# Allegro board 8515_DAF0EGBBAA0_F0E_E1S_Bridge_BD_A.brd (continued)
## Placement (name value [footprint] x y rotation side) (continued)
R728  22  [R0402-0201]  116.84 29.34 180 bottom
R729  22  [R0402-0201]  127.38 27.69 90 top
R730  4.7K  [R0402-0201]  127.38 29.72 90 top
R731  4.7K  [R0402-0201]  127.38 29.72 90 bottom
R733  4.7K  [R0402-0201]  120.27 27.69 270 bottom
R734  4.7K  [R0402-0201]  126.36 27.69 90 bottom
R735  4.7K  [R0402-0201]  122.3 29.72 270 bottom
R736  4.7K  [R0402-0201]  120.27 29.72 90 bottom
R737  4.7K  [R0402-0201]  121.28 29.72 90 bottom
R738  4.7K  [R0402-0201]  124.33 29.72 90 bottom
R746  2.87K  [R0402-0201]  115.44 49.02 0 top
R747  2.87K  [R0402-0201]  117.47 51.99 180 top
R749  2K  [R0402-0201]  115.44 48.01 180 top
R750  2K  [R0402-0201]  117.47 51.05 0 top
R751  2.87K  [R0402-0201]  117.47 51.99 180 bottom
R752  60.4K  [R0402-0201]  117.22 36.45 90 top
R753  2K  [R0402-0201]  117.47 51.05 0 bottom
R754  10K  [R0402-0201]  118.24 36.45 270 top
R755  60.4K  [R0402-0201]  115.44 38.1 0 bottom
R756  10K  [R0402-0201]  115.44 37.08 180 bottom
R757  60.4K  [R0402-0201]  115.44 38.1 0 top
R758  10K  [R0402-0201]  115.44 37.08 180 top
R759  60.4K  [R0402-0201]  116.46 42.01 270 top
R760  10K  [R0402-0201]  116.13 40.61 180 top
R765  60.4K  [R0402-0201]  119.51 49.02 180 top
R766  60.4K  [R0402-0201]  117.47 49.02 180 top
R767  2.87K  [R0402-0201]  117.47 49.02 180 bottom
R768  10K  [R0402-0201]  119.51 48.01 0 top
R769  10K  [R0402-0201]  117.47 48.01 0 top
R770  2K  [R0402-0201]  117.47 48.01 0 bottom
R771  2.87K  [R0402-0201]  119.51 49.02 180 bottom
R772  2K  [R0402-0201]  119.51 48.01 0 bottom
R773  4.7K  [R0402-0201]  135.64 47.37 90 top
R774  4.7K  [R0402-0201]  132.59 47.37 90 bottom
R775  4.7K  [R0402-0201]  135.64 47.37 90 bottom
R776  4.7K  [R0402-0201]  144.32 37.8 270 bottom
R777  4.7K  [R0402-0201]  135.64 50.04 270 top
R778  300K  [R0402-0201]  132.53 50.04 90 bottom
R779  4.7K  [R0402-0201]  135.64 50.04 270 bottom
R780  4.7K  [R0402-0201]  145.39 37.8 90 bottom
R781  4.7K  [R0402-0201]  126.36 52.07 270 top
R782  4.7K  [R0402-0201]  123.19 47.37 90 top
R783  4.7K  [R0402-0201]  133.6 47.37 90 top
R784  4.7K  [R0402-0201]  125.22 52.07 90 top
R785  4.7K  [R0402-0201]  124.21 50.04 90 top
R786  300K  [R0402-0201]  123.19 50.04 270 top
R787  4.7K  [R0402-0201]  133.48 50.04 270 top
R788  4.7K  [R0402-0201]  128.52 47.37 270 top
R789  4.7K  [R0402-0201]  124.21 47.37 90 top
R790  4.7K  [R0402-0201]  123.32 29.72 270 bottom
R791  4.7K  [R0402-0201]  126.36 29.72 270 bottom
R792  22  [R0402-0201]  11.33 12.57 270 top
R793  22  [R0402-0201]  14.99 12.57 270 top
R794  22  [R0402-0201]  118.87 33.02 180 bottom
R795  22  [R0402-0201]  135.18 26.37 270 bottom
R796  22  [R0402-0201]  136.09 26.37 270 bottom
R797  22  [R0402-0201]  135.42 20.8 180 bottom
R4580  4.7K  [R0402-0201]  130.18 55.5 180 top
R4581  4.7K  [R0402-0201]  130.18 56.52 180 top
R4582  4.7K  [R0402-0201]  130.18 60.58 180 top
R4583  4.7K  [R0402-0201]  130.18 58.55 180 top
R4584  22  [R0402-0201]  130.18 54.48 180 top
R4585  22  [R0402-0201]  130.18 57.53 180 top
R4586  22  [R0402-0201]  130.18 59.56 180 top
R4587  22  [R0402-0201]  130.18 61.59 180 top
R4588  2K  [R0402-0201]  117.86 38.86 0 top
R4589  22  [R0402-0201]  129.41 29.72 90 bottom
R4591  22  [R0402-0201]  135.42 18.08 180 bottom
R4592  22  [R0402-0201]  135.42 19 180 bottom
R4593  22  [R0402-0201]  118.31 12.53 90 top
R4594  22  [R0402-0201]  129.05 11.67 0 top
R4595  22  [R0402-0201]  113.33 13.67 0 top
R4596  22  [R0402-0201]  115.82 10.82 0 top
R4597  4.7K  [R0402-0201]  135.42 19.91 180 bottom
R4598  4.7K  [R0402-0201]  113.33 14.58 0 top
R4599  4.7K  [R0402-0201]  117.88 10.82 0 top
R4600  4.7K  [R0402-0201]  138.71 22.53 180 bottom
R4601  4.7K  [R0402-0201]  138.71 21.62 180 bottom
R4602  22  [R0402-0201]  12.24 12.57 270 top
R4603  22  [R0402-0201]  14.07 12.57 270 top
R4604  4.7K  [R0402-0201]  142.44 28.29 90 bottom
R4605  4.7K  [R0402-0201]  141.53 28.29 90 bottom
R4607  22  [R0402-0201]  27.53 12.45 270 top
R4608  22  [R0402-0201]  117.88 13.49 90 bottom
R4609  4.7K  [R0402-0201]  109.02 15.19 0 top
R4610  100  [R0402-0201]  108.99 16.18 0 top
R4611  22  [R0402-0201]  107.59 14.55 90 top
R4612  0  [R0402-0201]  118.9 13.49 270 bottom
R4613  1K  [R0402-0201]  134.62 50.04 270 bottom
R4614  47K  [R0402-0201]  133.6 50.04 270 bottom
R4615  4.7K  [R0402-0201]  133.6 47.37 270 bottom
R4616  4.7K  [R0402-0201]  128.52 47.37 270 bottom
R4617  4.7K  [R0402-0201]  129.54 47.37 270 bottom
R4618  4.7K  [R0402-0201]  131.57 50.04 270 bottom
R4619  0  [R0402-0201]  23.65 53.39 180 bottom
R4620  0  [R0402-0201]  19.33 54.28 270 bottom
R4621  10K  [R0402-0201]  18.92 51.89 0 bottom
R4622  1K  [R0402-0201]  23.65 55.22 0 bottom
R4623  0  [R0402-0201]  47.29 50.85 180 bottom
R4624  0  [R0402-0201]  42.19 54.2 0 bottom
R4625  10K  [R0402-0201]  42.19 52.37 0 bottom
R4626  1K  [R0402-0201]  47.29 52.68 180 bottom
R4627  0  [R0402-0201]  71.48 55.17 90 bottom
R4628  0  [R0402-0201]  68.2 59.82 180 bottom
R4629  10K  [R0402-0201]  68.1 57.99 0 bottom
R4630  1K  [R0402-0201]  73.3 55.17 270 bottom
R4631  0  [R0402-0201]  98.55 51.38 180 bottom
R4632  0  [R0402-0201]  91.19 53.04 180 bottom
R4633  10K  [R0402-0201]  91.19 54.1 0 bottom
R4634  1K  [R0402-0201]  98.55 53.21 0 bottom
R4635  0  [R0402-0201]  23.65 54.31 0 bottom
R4636  0  [R0402-0201]  47.29 51.77 180 bottom
R4637  0  [R0402-0201]  72.39 55.17 270 bottom
R4638  0  [R0402-0201]  98.55 52.3 0 bottom
R4639  10K  [R0402-0201]  11.68 37.49 180 top
R4640  0  [R0402-0201]  6.35 36.63 180 top
R4641  0  [R0402-0201]  11.68 36.58 0 top
R4642  0  [R0402-0201]  6.35 35.71 0 top
R4643  1K  [R0402-0201]  6.35 37.54 180 top
R4644  10K  [R0402-0201]  45.21 40.59 0 bottom
R4645  0  [R0402-0201]  45.09 44.83 180 bottom
R4646  0  [R0402-0201]  45.21 42.39 180 bottom
R4647  0  [R0402-0201]  45.1 43.89 0 bottom
R4648  1K  [R0402-0201]  45.09 45.75 180 bottom
R4649  10K  [R0402-0201]  59.87 22.71 0 top
R4650  0  [R0402-0201]  62.66 19.32 180 top
R4651  0  [R0402-0201]  60.76 24.16 270 top
R4652  0  [R0402-0201]  62.66 18.4 180 top
R4653  1K  [R0402-0201]  62.66 20.23 180 top
R4654  10K  [R0402-0201]  92.46 28.02 180 bottom
R4655  0  [R0402-0201]  86.28 27 0 bottom
R4656  0  [R0402-0201]  92.46 26.19 0 bottom
R4657  0  [R0402-0201]  86.28 27.91 0 bottom
R4658  1K  [R0402-0201]  86.28 26.09 180 bottom
R4659  4.7K  [R0402-0201]  138.71 24.36 180 bottom
R4660  4.7K  [R0402-0201]  138.71 23.44 180 bottom
R4661  4.7K  [R0402-0201]  138.71 20.7 180 bottom
R4662  4.7K  [R0402-0201]  145.21 19.86 180 bottom
R4663  4.7K  [R0402-0201]  145.21 20.78 180 bottom
R4664  4.7K  [R0402-0201]  145.21 21.69 180 bottom
R4665  4.7K  [R0402-0201]  145.21 22.61 180 bottom
R4666  4.7K  [R0402-0201]  145.21 23.52 180 bottom
R4667  4.7K  [R0402-0201]  145.21 24.46 180 bottom
R4668  4.7K  [R0402-0201]  145.21 25.78 180 bottom
R4669  4.7K  [R0402-0201]  145.16 28.09 180 bottom
R4670  0  [R0402-0201]  141.94 34.84 0 bottom
R4671  0  [R0402-0201]  2.16 25.96 0 bottom
U3  TPS259540DSGR  [WSON8_TH_0-5_2X2XA]  23.29 58.12 270 top
U4  TPS259540DSGR  [WSON8_TH_0-5_2X2XA]  48.06 57.35 270 top
U5  TPS259540DSGR  [WSON8_TH_0-5_2X2XA]  73.58 57.38 270 top
U6  TPS259540DSGR  [WSON8_TH_0-5_2X2XA]  99.06 57.53 270 top
U7  TPS259520DSGR  [WSON8_TH_0-5_2X2XA]  14.38 45.42 0 top
U8  TPS259520DSGR  [WSON8_TH_0-5_2X2XA]  43.08 43.36 0 top
U9  TPS259520DSGR  [WSON8_TH_0-5_2X2XA]  93.34 32.89 0 top
U10  TPS259520DSGR  [WSON8_TH_0-5_2X2XA]  65.99 26.49 0 top
U11  INA230AIRGTR  [QFN16_THXI]  14.73 50.55 0 top
U12  INA230AIRGTR  [QFN16_THXI]  40.87 48.79 0 top
U13  INA230AIRGTR  [QFN16_THXI]  66.52 31.52 0 top
U14  INA230AIRGTR  [QFN16_THXI]  94.21 39.65 0 top
U15  M24128-BWMN6TP  [SOIC8XH]  124.03 59.59 180 top
U16  TMP75  [MSOP8]  92.68 48.87 180 top
U17  2N7002KW  [SOT323XB]  143.99 32.72 270 bottom
U18  TPS259521DSGR  [WSON8_TH_0-5_2X2XA]  120.93 17.48 90 top
U22  MAX15090BEWI+T  [BGA28_0-5_3-525X2-065]  18.21 57.96 0 top
U23  MAX15090BEWI+T  [BGA28_0-5_3-525X2-065]  42.98 57.45 0 top
U24  MAX15090BEWI+T  [BGA28_0-5_3-525X2-065]  68.5 57.1 0 top
U25  MAX15090BEWI+T  [BGA28_0-5_3-525X2-065]  93.98 57.25 0 top
U26  MAX15090BEWI+T  [BGA28_0-5_3-525X2-065]  14.25 40.54 90 top
U27  MAX15090BEWI+T  [BGA28_0-5_3-525X2-065]  43.33 38.46 90 top
U28  MAX15090BEWI+T  [BGA28_0-5_3-525X2-065]  65.71 21.62 90 top
U29  MAX15090BEWI+T  [BGA28_0-5_3-525X2-065]  92.71 27.76 90 top
U30  MAX15090BEWI+T  [BGA28_0-5_3-525X2-065]  128.19 17.53 180 top
U32  9DBL0452BKILFT  [VFQFPN32_TH_0-5_5X5]  39.37 27.94 0 top
U33  MAX15090BEWI+T  [BGA28_0-5_3-525X2-065]  9.83 29.41 180 top
U34  MP5022AGQV-Z  [QFN22_TH_3X5]  16.8 31.96 180 top
U35  AST1030A1-GP  [BGA256_0-8_13X13]  127.42 38.5 0 top
U36  RT9059GQW  [DFN10_THXE]  124.53 24.45 0 top
U42  NL17SZ08DFT2G  [SC70-5XA]  116.2 12.78 0 top
U43  NL17SZ08DFT2G  [SC70-5XA]  120.85 11.56 0 top
U44  PCA9537DP  [MSOP10]  141.5 23.9 90 bottom
U45  74LVC1G17GW  [TSSOP5]  107.42 19.68 90 top
U46  NL17SZ08DFT2G  [SC70-5XA]  115.56 13.2 180 bottom
U47  74LVC1G17GW  [TSSOP5]  109.65 12.45 270 top
U48  PCA9555  [TSSOP24]  139.5 24.03 0 top
X1  TP_TDR_4P_DIP  [MPKT4_H025P0200]  -9.02 12.71 0 bottom
X2  TP_TDR_4P_DIP  [MPKT4_H025P0200]  -45.21 15.25 180 bottom
X3  TP_TDR_4P_DIP  [MPKT4_H025P0200]  -9.02 20.97 0 top
X4  TP_TDR_4P_DIP  [MPKT4_H025P0200]  -45.21 18.43 180 top
X5  TP_TDR_4P_DIP  [MPKT4_H025P0200]  -48.67 116.64 180 bottom
X6  TP_TDR_4P_DIP  [MPKT4_H025P0200]  -8.67 114.1 0 bottom
X7  TP_TDR_4P_DIP  [MPKT4_H025P0200]  -48.67 119.82 180 top
X8  TP_TDR_4P_DIP  [MPKT4_H025P0200]  -8.67 122.36 0 top

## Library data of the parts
C48-C92 C96 C102 C105 C108-C113 C115 C116 C118 C119 C121 C122 C124 C125 C127-C132 C147-C150 C157-C172 C176-C180 C202-C237 C239 C240 C243 C244 C246 C247 C249-C252 C284-C304 C306-C322 PC72 = CAP_NP
D2 D3 D6 D7 D21 = SMDJ60A
D4 D5 D8 D9 = SCHOTTKY_AC
D10 = LED_12
D11 D24 = LED_0
D22 = SPL1040PT
D23 = ZENER_12
D25 = DIODE
DM4-DM6 ME1 = ME_DUMMY_SYMBOL
GF1 = FCONN168_623403212
GF2 = FCONN140_623403242
H3-H17 = HOLE
J1 = SCONN3_51471181
J2 = CONN10_878311019
J4-J7 = SCONN56_ME1305610101011
J8-J11 J13 J14 J17-J26 = PICOPROBE_B
J12 J15 J16 J27 = TDR_3P_TH2
J29 J30 = DIP_2PIN
L4-L9 = L
OSC1 = OSC-4
PR76 R2 R5-R8 R10 R11 R14-R16 R18-R24 R90 R169-R185 R189-R204 R209-R211 R213-R219 R221-R223 R226-R234 R236-R238 R241-R249 R251-R253 R256-R264 R266-R268 R271-R276 R279-R288 R291-R298 R305-R309 R319 R410-R414 R417 R426-R429 R438-R467 R473-R481 R490-R514 R518-R542 R544 R545 R548 R550-R557 R561-R579 R584 R586 R590 R591 R598-R600 R602 R604 R605 R607 R608 R611 R613 R617 R619-R636 R639-R641 R646 R651 R659-R661 R663-R667 R679-R681 R685 R690 R691 R694-R701 R707-R714 R723-R731 R733-R738 R746 R747 R749-R760 R765-R797 R4588 R4589 R4591-R4605 R4607-R4612 R4619-R4671 = R
Q1 Q2 = MOSFET_NCH_DUAL: signal model: MOSFET_DUAL_6P_SOT363XD_IC_2N70_2N7002KDW
Q3 Q4 U17 = MOSFET_NCH_GDS_ESD_PROTECTED
Q5-Q12 = SSM6N7002KFU
R1 R9 R12 R13 R17 R224 R225 R239 R240 R254 R255 R269 R270 R277 R278 R289 R290 R400-R402 R433 = R: signal model: R_R0402-0201_DISCRETE_22_22
R220 R235 R250 R265 = Q_SP_RES4P
R418-R425 = R: signal model: R_R0402-0201_DISCRETE_33.2_33.2
R559 R560 = R: signal model: R_R0402-0201_DISCRETE_0_0
R596 = R: signal model: R_R0402-0201_DISCRETE_CS21002FB_1K
R674 R4584-R4587 = R: signal model: R_R0402-0201_DISCRETE_CS02202FB_22
R675 = R: signal model: R_R0402-0201_DISCRETE_CS41002JB_100K
R4580-R4583 = R: signal model: R_R0402-0201_DISCRETE_CS31002FB_10K
R4613-R4618 = R: signal model: R_R0402
U3-U10 U18 = TPS259521DSGR
U11-U14 = INA230AIRGTR
U15 = M24128
U16 = TMP75AIDGKR
U22-U30 U33 = MAX15090BEWIT
U32 = 9DBL0452BKILFT
U34 = MP5022AGQVZ
U35 = AST1030A1GP
U36 = RT9059GQW
U42 U43 U46 = NL17SZ08DFT2G
U44 = PCA9537
U45 U47 = SN74LVC1G07
U48 = PCA9555
X1-X8 = TP_TDR_4P_FTS: User Part Number: TP15

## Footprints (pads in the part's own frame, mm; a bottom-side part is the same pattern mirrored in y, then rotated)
BGA28_0-5_3-525X2-065
  round 0.229 smd: A1(-1.5,0.75) A2(-1,0.75) A3(-0.5,0.75) A4(0,0.75) A5(0.5,0.75) A6(1,0.75) A7(1.5,0.75) B1(-1.5,0.25) B2(-1,0.25) B3(-0.5,0.25) B4(0,0.25) B5(0.5,0.25) B6(1,0.25) B7(1.5,0.25) C1(-1.5,-0.25) C2(-1,-0.25) C3(-0.5,-0.25) C4(0,-0.25) C5(0.5,-0.25) C6(1,-0.25) C7(1.5,-0.25) D1(-1.5,-0.75) D2(-1,-0.75) D3(-0.5,-0.75) D4(0,-0.75) D5(0.5,-0.75) D6(1,-0.75) D7(1.5,-0.75)
BGA256_0-8_13X13
  round 0.406 smd: A1(-6,6) A2(-5.2,6) A3(-4.4,6) A4(-3.6,6) A5(-2.8,6) A6(-2,6) A7(-1.2,6) A8(-0.4,6) A9(0.4,6) A10(1.2,6) A11(2,6) A12(2.8,6) A13(3.6,6) A14(4.4,6) A15(5.2,6) A16(6,6) B1(-6,5.2) B2(-5.2,5.2) B3(-4.4,5.2) B4(-3.6,5.2) B5(-2.8,5.2) B6(-2,5.2) B7(-1.2,5.2) B8(-0.4,5.2) B9(0.4,5.2) B10(1.2,5.2) B11(2,5.2) B12(2.8,5.2) B13(3.6,5.2) B14(4.4,5.2) B15(5.2,5.2) B16(6,5.2) C1(-6,4.4) C2(-5.2,4.4) C3(-4.4,4.4) C4(-3.6,4.4) C5(-2.8,4.4) C6(-2,4.4) C7(-1.2,4.4) C8(-0.4,4.4) C9(0.4,4.4) C10(1.2,4.4) C11(2,4.4) C12(2.8,4.4) C13(3.6,4.4) C14(4.4,4.4) C15(5.2,4.4) C16(6,4.4) D1(-6,3.6) D2(-5.2,3.6) D3(-4.4,3.6) D4(-3.6,3.6) D5(-2.8,3.6) D6(-2,3.6) D7(-1.2,3.6) D8(-0.4,3.6) D9(0.4,3.6) D10(1.2,3.6) D11(2,3.6) D12(2.8,3.6) D13(3.6,3.6) D14(4.4,3.6) D15(5.2,3.6) D16(6,3.6) E1(-6,2.8) E2(-5.2,2.8) E3(-4.4,2.8) E4(-3.6,2.8) E5(-2.8,2.8) E6(-2,2.8) E7(-1.2,2.8) E8(-0.4,2.8) E9(0.4,2.8) E10(1.2,2.8) E11(2,2.8) E12(2.8,2.8) E13(3.6,2.8) E14(4.4,2.8) E15(5.2,2.8) E16(6,2.8) F1(-6,2) F2(-5.2,2) F3(-4.4,2) F4(-3.6,2) F5(-2.8,2) F6(-2,2) F7(-1.2,2) F8(-0.4,2) F9(0.4,2) F10(1.2,2) F11(2,2) F12(2.8,2) F13(3.6,2) F14(4.4,2) F15(5.2,2) F16(6,2) G1(-6,1.2) G2(-5.2,1.2) G3(-4.4,1.2) G4(-3.6,1.2) G5(-2.8,1.2) G6(-2,1.2) G7(-1.2,1.2) G8(-0.4,1.2) G9(0.4,1.2) G10(1.2,1.2) G11(2,1.2) G12(2.8,1.2) G13(3.6,1.2) G14(4.4,1.2) G15(5.2,1.2) G16(6,1.2) H1(-6,0.4) H2(-5.2,0.4) H3(-4.4,0.4) H4(-3.6,0.4) H5(-2.8,0.4) H6(-2,0.4) H7(-1.2,0.4) H8(-0.4,0.4) H9(0.4,0.4) H10(1.2,0.4) H11(2,0.4) H12(2.8,0.4) H13(3.6,0.4) H14(4.4,0.4) H15(5.2,0.4) H16(6,0.4) J1(-6,-0.4) J2(-5.2,-0.4) J3(-4.4,-0.4) J4(-3.6,-0.4) J5(-2.8,-0.4) J6(-2,-0.4) J7(-1.2,-0.4) J8(-0.4,-0.4) J9(0.4,-0.4) J10(1.2,-0.4) J11(2,-0.4) J12(2.8,-0.4) J13(3.6,-0.4) J14(4.4,-0.4) J15(5.2,-0.4) J16(6,-0.4) K1(-6,-1.2) K2(-5.2,-1.2) K3(-4.4,-1.2) K4(-3.6,-1.2) K5(-2.8,-1.2) K6(-2,-1.2) K7(-1.2,-1.2) K8(-0.4,-1.2) K9(0.4,-1.2) K10(1.2,-1.2) K11(2,-1.2) K12(2.8,-1.2) K13(3.6,-1.2) K14(4.4,-1.2) K15(5.2,-1.2) K16(6,-1.2) L1(-6,-2) L2(-5.2,-2) L3(-4.4,-2) L4(-3.6,-2) L5(-2.8,-2) L6(-2,-2) L7(-1.2,-2) L8(-0.4,-2) L9(0.4,-2) L10(1.2,-2) L11(2,-2) L12(2.8,-2) L13(3.6,-2) L14(4.4,-2) L15(5.2,-2) L16(6,-2) M1(-6,-2.8) M2(-5.2,-2.8) M3(-4.4,-2.8) M4(-3.6,-2.8) M5(-2.8,-2.8) M6(-2,-2.8) M7(-1.2,-2.8) M8(-0.4,-2.8) M9(0.4,-2.8) M10(1.2,-2.8) M11(2,-2.8) M12(2.8,-2.8) M13(3.6,-2.8) M14(4.4,-2.8) M15(5.2,-2.8) M16(6,-2.8) N1(-6,-3.6) N2(-5.2,-3.6) N3(-4.4,-3.6) N4(-3.6,-3.6) N5(-2.8,-3.6) N6(-2,-3.6) N7(-1.2,-3.6) N8(-0.4,-3.6) N9(0.4,-3.6) N10(1.2,-3.6) N11(2,-3.6) N12(2.8,-3.6) N13(3.6,-3.6) N14(4.4,-3.6) N15(5.2,-3.6) N16(6,-3.6) P1(-6,-4.4) P2(-5.2,-4.4) P3(-4.4,-4.4) P4(-3.6,-4.4) P5(-2.8,-4.4) P6(-2,-4.4) P7(-1.2,-4.4) P8(-0.4,-4.4) P9(0.4,-4.4) P10(1.2,-4.4) P11(2,-4.4) P12(2.8,-4.4) P13(3.6,-4.4) P14(4.4,-4.4) P15(5.2,-4.4) P16(6,-4.4) R1(-6,-5.2) R2(-5.2,-5.2) R3(-4.4,-5.2) R4(-3.6,-5.2) R5(-2.8,-5.2) R6(-2,-5.2) R7(-1.2,-5.2) R8(-0.4,-5.2) R9(0.4,-5.2) R10(1.2,-5.2) R11(2,-5.2) R12(2.8,-5.2) R13(3.6,-5.2) R14(4.4,-5.2) R15(5.2,-5.2) R16(6,-5.2) T1(-6,-6) T2(-5.2,-6) T3(-4.4,-6) T4(-3.6,-6) T5(-2.8,-6) T6(-2,-6) T7(-1.2,-6) T8(-0.4,-6) T9(0.4,-6) T10(1.2,-6) T11(2,-6) T12(2.8,-6) T13(3.6,-6) T14(4.4,-6) T15(5.2,-6) T16(6,-6)
C0402
  rect 0.457x0.508 smd: 1(-0.4,0) 2(0.4,0)
C0402-0201
  custom 0.125x0.125 smd: 1(-0.4,0) 2(0.4,0)
C0402_OCTAGONXA
  custom 0.104x0.104 smd: 1(-0.4,0) 2(0.4,0)
C0603
  rect 0.813x0.711 smd: 1(-0.737,0) 2(0.737,0)
C0805_H57
  rect 1.016x1.27 smd: 1(-0.889,0) 2(0.889,0)
C0805_H61
  rect 1.118x1.372 smd: 1(-0.95,0) 2(0.95,0)
CON_F56S2H4D_P0-6W4-6_LUHXA
  round 1.118 hole 1.118 unplated: (-1.75,9.815) (0,-9.815)
  rect 1.27x0.381 smd: A1(2.3,7.995) A2(2.3,7.395) A3(2.3,6.795) A4(2.3,6.195) A5(2.3,5.595) A6(2.3,4.995) A7(2.3,4.395) A8(2.3,3.795) A9(2.3,3.195) A10(2.3,2.595) A11(2.3,1.995) A12(2.3,1.395) A13(2.3,0.795) A14(2.3,0.195) A15(2.3,-0.405) A16(2.3,-1.005) A17(2.3,-1.605) A18(2.3,-2.205) A19(2.3,-2.805) A20(2.3,-3.405) A21(2.3,-4.005) A22(2.3,-4.605) A23(2.3,-5.205) A24(2.3,-5.805) A25(2.3,-6.405) A26(2.3,-7.005) A27(2.3,-7.605) A28(2.3,-8.205) B1(-2.3,7.995) B2(-2.3,7.395) B3(-2.3,6.795) B4(-2.3,6.195) B5(-2.3,5.595) B6(-2.3,4.995) B7(-2.3,4.395) B8(-2.3,3.795) B9(-2.3,3.195) B10(-2.3,2.595) B11(-2.3,1.995) B12(-2.3,1.395) B13(-2.3,0.795) B14(-2.3,0.195) B15(-2.3,-0.405) B16(-2.3,-1.005) B17(-2.3,-1.605) B18(-2.3,-2.205) B19(-2.3,-2.805) B20(-2.3,-3.405) B21(-2.3,-4.005) B22(-2.3,-4.605) B23(-2.3,-5.205) B24(-2.3,-5.805) B25(-2.3,-6.405) B26(-2.3,-7.005) B27(-2.3,-7.605) B28(-2.3,-8.205)
  oval 3.48x1.626 hole 2.464x1.118: G1(0,11.365) G2(0,-11.365)
D_SMCJ170
  rect 2.515x3.302 smd: 1(-3.4,0) 2(3.4,0)
DFN10_THXE
  rect 0.914x0.279 smd: 1(-1.55,1) 2(-1.55,0.5) 3(-1.55,0) 4(-1.55,-0.5) 5(-1.55,-1) 6(1.55,-1) 7(1.55,-0.5) 8(1.55,0) 9(1.55,0.5) 10(1.55,1)
  rect 1.753x2.667 smd: TH(0,0)
GOLD_140P_6-2340324-2
  rect 0.381x2.134 smd: A1(-18.205,-4.135) A4(-16.405,-4.135) A7(-14.605,-4.135) A10(-12.805,-4.135) A13(-11.005,-4.135) A16(-9.205,-4.135) A19(-7.405,-4.135) A22(-5.605,-4.135) A25(-3.805,-4.135) A28(-2.005,-4.135) A29(2.005,-4.135) A32(3.805,-4.135) A35(5.605,-4.135) A38(7.405,-4.135) A41(9.205,-4.135) A43(14.715,-4.135) A46(16.515,-4.135) A49(18.315,-4.135) A52(20.115,-4.135) A55(21.915,-4.135) A58(23.715,-4.135) A61(25.515,-4.135) A64(27.315,-4.135) A67(29.115,-4.135) A70(30.915,-4.135) B1(-18.205,-4.135) B4(-16.405,-4.135) B7(-14.605,-4.135) B10(-12.805,-4.135) B13(-11.005,-4.135) B16(-9.205,-4.135) B19(-7.405,-4.135) B22(-5.605,-4.135) B25(-3.805,-4.135) B28(-2.005,-4.135) B29(2.005,-4.135) B32(3.805,-4.135) B35(5.605,-4.135) B38(7.405,-4.135) B41(9.205,-4.135) B43(14.715,-4.135) B46(16.515,-4.135) B49(18.315,-4.135) B52(20.115,-4.135) B55(21.915,-4.135) B58(23.715,-4.135) B61(25.515,-4.135) B64(27.315,-4.135) B67(29.115,-4.135) B70(30.915,-4.135)
  rect 0.381x1.727 smd: A2(-17.605,-3.935) A3(-17.005,-3.935) A5(-15.805,-3.935) A6(-15.205,-3.935) A8(-14.005,-3.935) A9(-13.405,-3.935) A11(-12.205,-3.935) A12(-11.605,-3.935) A14(-10.405,-3.935) A15(-9.805,-3.935) A17(-8.605,-3.935) A18(-8.005,-3.935) A20(-6.805,-3.935) A21(-6.205,-3.935) A23(-5.005,-3.935) A24(-4.405,-3.935) A26(-3.205,-3.935) A27(-2.605,-3.935) A30(2.605,-3.935) A31(3.205,-3.935) A33(4.405,-3.935) A34(5.005,-3.935) A36(6.205,-3.935) A37(6.805,-3.935) A39(8.005,-3.935) A40(8.605,-3.935) A42(9.805,-3.935) A44(15.315,-3.935) A45(15.915,-3.935) A47(17.115,-3.935) A48(17.715,-3.935) A50(18.915,-3.935) A51(19.515,-3.935) A53(20.715,-3.935) A54(21.315,-3.935) A56(22.515,-3.935) A57(23.115,-3.935) A59(24.315,-3.935) A60(24.915,-3.935) A62(26.115,-3.935) A63(26.715,-3.935) A65(27.915,-3.935) A66(28.515,-3.935) A68(29.715,-3.935) A69(30.315,-3.935) B2(-17.605,-3.935) B3(-17.005,-3.935) B5(-15.805,-3.935) B6(-15.205,-3.935) B8(-14.005,-3.935) B9(-13.405,-3.935) B11(-12.205,-3.935) B12(-11.605,-3.935) B14(-10.405,-3.935) B15(-9.805,-3.935) B17(-8.605,-3.935) B18(-8.005,-3.935) B20(-6.805,-3.935) B21(-6.205,-3.935) B23(-5.005,-3.935) B24(-4.405,-3.935) B26(-3.205,-3.935) B27(-2.605,-3.935) B30(2.605,-3.935) B31(3.205,-3.935) B33(4.405,-3.935) B34(5.005,-3.935) B36(6.205,-3.935) B37(6.805,-3.935) B39(8.005,-3.935) B40(8.605,-3.935) B42(9.805,-3.935) B44(15.315,-3.935) B45(15.915,-3.935) B47(17.115,-3.935) B48(17.715,-3.935) B50(18.915,-3.935) B51(19.515,-3.935) B53(20.715,-3.935) B54(21.315,-3.935) B56(22.515,-3.935) B57(23.115,-3.935) B59(24.315,-3.935) B60(24.915,-3.935) B62(26.115,-3.935) B63(26.715,-3.935) B65(27.915,-3.935) B66(28.515,-3.935) B68(29.715,-3.935) B69(30.315,-3.935)
GOLD_168P_6-2340321-2
  rect 0.381x2.134 smd: A1(-18.205,-4.135) A4(-16.405,-4.135) A7(-14.605,-4.135) A10(-12.805,-4.135) A13(-11.005,-4.135) A16(-9.205,-4.135) A19(-7.405,-4.135) A22(-5.605,-4.135) A25(-3.805,-4.135) A28(-2.005,-4.135) A29(2.005,-4.135) A32(3.805,-4.135) A35(5.605,-4.135) A38(7.405,-4.135) A41(9.205,-4.135) A43(14.715,-4.135) A46(16.515,-4.135) A49(18.315,-4.135) A52(20.115,-4.135) A55(21.915,-4.135) A58(23.715,-4.135) A61(25.515,-4.135) A64(27.315,-4.135) A67(29.115,-4.135) A70(30.915,-4.135) B1(-18.205,-4.135) B4(-16.405,-4.135) B7(-14.605,-4.135) B10(-12.805,-4.135) B13(-11.005,-4.135) B16(-9.205,-4.135) B19(-7.405,-4.135) B22(-5.605,-4.135) B25(-3.805,-4.135) B28(-2.005,-4.135) B29(2.005,-4.135) B32(3.805,-4.135) B35(5.605,-4.135) B38(7.405,-4.135) B41(9.205,-4.135) B43(14.715,-4.135) B46(16.515,-4.135) B49(18.315,-4.135) B52(20.115,-4.135) B55(21.915,-4.135) B58(23.715,-4.135) B61(25.515,-4.135) B64(27.315,-4.135) B67(29.115,-4.135) B70(30.915,-4.135) OCP_A6(-27.4,-4.135) OCP_A10(-25,-4.135) OCP_A13(-23.2,-4.135) OCP_B10(-25,-4.135) OCP_B13(-23.2,-4.135)
  rect 0.381x1.727 smd: A2(-17.605,-3.935) A3(-17.005,-3.935) A5(-15.805,-3.935) A6(-15.205,-3.935) A8(-14.005,-3.935) A9(-13.405,-3.935) A11(-12.205,-3.935) A12(-11.605,-3.935) A14(-10.405,-3.935) A15(-9.805,-3.935) A17(-8.605,-3.935) A18(-8.005,-3.935) A20(-6.805,-3.935) A21(-6.205,-3.935) A23(-5.005,-3.935) A24(-4.405,-3.935) A26(-3.205,-3.935) A27(-2.605,-3.935) A30(2.605,-3.935) A31(3.205,-3.935) A33(4.405,-3.935) A34(5.005,-3.935) A36(6.205,-3.935) A37(6.805,-3.935) A39(8.005,-3.935) A40(8.605,-3.935) A42(9.805,-3.935) A44(15.315,-3.935) A45(15.915,-3.935) A47(17.115,-3.935) A48(17.715,-3.935) A50(18.915,-3.935) A51(19.515,-3.935) A53(20.715,-3.935) A54(21.315,-3.935) A56(22.515,-3.935) A57(23.115,-3.935) A59(24.315,-3.935) A60(24.915,-3.935) A62(26.115,-3.935) A63(26.715,-3.935) A65(27.915,-3.935) A66(28.515,-3.935) A68(29.715,-3.935) A69(30.315,-3.935) B2(-17.605,-3.935) B3(-17.005,-3.935) B5(-15.805,-3.935) B6(-15.205,-3.935) B8(-14.005,-3.935) B9(-13.405,-3.935) B11(-12.205,-3.935) B12(-11.605,-3.935) B14(-10.405,-3.935) B15(-9.805,-3.935) B17(-8.605,-3.935) B18(-8.005,-3.935) B20(-6.805,-3.935) B21(-6.205,-3.935) B23(-5.005,-3.935) B24(-4.405,-3.935) B26(-3.205,-3.935) B27(-2.605,-3.935) B30(2.605,-3.935) B31(3.205,-3.935) B33(4.405,-3.935) B34(5.005,-3.935) B36(6.205,-3.935) B37(6.805,-3.935) B39(8.005,-3.935) B40(8.605,-3.935) B42(9.805,-3.935) B44(15.315,-3.935) B45(15.915,-3.935) B47(17.115,-3.935) B48(17.715,-3.935) B50(18.915,-3.935) B51(19.515,-3.935) B53(20.715,-3.935) B54(21.315,-3.935) B56(22.515,-3.935) B57(23.115,-3.935) B59(24.315,-3.935) B60(24.915,-3.935) B62(26.115,-3.935) B63(26.715,-3.935) B65(27.915,-3.935) B66(28.515,-3.935) B68(29.715,-3.935) B69(30.315,-3.935) OCP_A1(-30.4,-3.935) OCP_A2(-29.8,-3.935) OCP_A3(-29.2,-3.935) OCP_A4(-28.6,-3.935) OCP_A5(-28,-3.935) OCP_A7(-26.8,-3.935) OCP_A8(-26.2,-3.935) OCP_A9(-25.6,-3.935) OCP_A11(-24.4,-3.935) OCP_A12(-23.8,-3.935) OCP_A14(-22.6,-3.935) OCP_B1(-30.4,-3.935) OCP_B2(-29.8,-3.935) OCP_B3(-29.2,-3.935) OCP_B4(-28.6,-3.935) OCP_B5(-28,-3.935) OCP_B6(-27.4,-3.935) OCP_B7(-26.8,-3.935) OCP_B8(-26.2,-3.935) OCP_B9(-25.6,-3.935) OCP_B11(-24.4,-3.935) OCP_B12(-23.8,-3.935) OCP_B14(-22.6,-3.935)
HEADER1X2XJ_H339
  rect 1.549x1.549 hole 1.041: 1(0,0)
  round 1.549 hole 1.041: 2(0,-2.54)
HEADER1X3SXE_H367
  rect 2.769x1.016 smd: 1(-1.375,2.54) 2(1.375,0) 3(-1.375,-2.54)
HEADER2X5SXM
  rect 2.591x0.711 smd: 1(-1.712,2.54) 2(1.712,2.54) 3(-1.712,1.27) 4(1.712,1.27) 5(-1.712,0) 6(1.712,0) 7(-1.712,-1.27) 8(1.712,-1.27) 9(-1.712,-2.54) 10(1.712,-2.54)
HOLE_C5D2B4_R2-23X5T_NPM
  custom 1.181x1.181 hole 2.007: 1(0,0)
HOLE_C7-5D3_5B7_OB7XC4-75TC3-5B_NPM_SPD
  custom 2.375x2.375 hole 3.023: 1(0,0)
HOLE_C8D3-3B10_NPM
  round 8.001 hole 3.302: 1(0,0)
HOLE_C10-2D6-4B10_R5-6X10B_NPB
  round 10.211 hole 6.401: 1(0,0)
L0402
  rect 0.457x0.508 smd: 1(-0.4,0) 2(0.4,0)
L0603
  rect 0.813x0.711 smd: 1(-0.737,0) 2(0.737,0)
L0805
  rect 1.118x1.372 smd: 1(-0.95,0) 2(0.95,0)
LED_19217_H22
  rect 0.813x0.813 smd: A(-0.75,0) C(0.75,0)
LED_LTSTS270KSKT
  rect 0.914x0.914 smd: 1(-0.9,0) 2(0.9,0)
MPKT4_H025P0200
  round 1.003 hole 0.25: 1(0,0) 4(0,-2.54)
  round 1.994 hole 0.25: 2(2.54,0) 3(2.54,-2.54)
MSOP8
  rect 1.422x0.356 smd: 1(-2.232,0.975) 2(-2.232,0.325) 3(-2.232,-0.325) 4(-2.232,-0.975) 5(2.232,-0.975) 6(2.232,-0.325) 7(2.232,0.325) 8(2.232,0.975)
MSOP10
  rect 1.448x0.279 smd: 1(-2.225,1) 2(-2.225,0.5) 3(-2.225,0) 4(-2.225,-0.5) 5(-2.225,-1) 6(2.225,-1) 7(2.225,-0.5) 8(2.225,0) 9(2.225,0.5) 10(2.225,1)
OSC4_FJ2500009
  rect 1.016x1.219 smd: 1(-0.65,0.85) 2(-0.65,-0.85) 3(0.65,-0.85) 4(0.65,0.85)
POWERDI5XA
  rect 1.397x1.422 smd: 1(-2.856,0.92) 2(-2.856,-0.92)
  rect 4.877x3.378 smd: 3(1.126,0)
QFN16_THXI
  rect 0.838x0.254 smd: 1(-1.475,0.75) 2(-1.475,0.25) 3(-1.475,-0.25) 4(-1.475,-0.75) 9(1.475,-0.75) 10(1.475,-0.25) 11(1.475,0.25) 12(1.475,0.75)
  rect 0.254x0.838 smd: 5(-0.75,-1.475) 6(-0.25,-1.475) 7(0.25,-1.475) 8(0.75,-1.475) 13(0.75,1.475) 14(0.25,1.475) 15(-0.25,1.475) 16(-0.75,1.475)
  rect 1.702x1.702 smd: TH(0,0)
QFN22_TH_3X5
  custom 0.062x0.062 smd: 1(-1.375,2)
  rect 0.813x0.254 smd: 2(-1.4,1.5) 3(-1.4,1) 4(-1.4,0.5) 5(-1.4,0) 6(-1.4,-0.5) 7(-1.4,-1) 8(-1.4,-1.5) 9(-1.4,-2) 12(1.4,-2) 13(1.4,-1.5) 14(1.4,-1) 15(1.4,-0.5) 16(1.4,0) 17(1.4,0.5) 18(1.4,1) 19(1.4,1.5) 20(1.4,2)
  rect 0.254x0.813 smd: 10(-0.5,-2.4) 11(0.5,-2.4)
  custom 0.231x0.231 smd: 21_22(0.5,2.338)
  rect 1.27x0.254 smd: 23(0,1.1) 24(0,0.2) 25(0,-0.7) 26(0,-1.6)
R0402-0201
  custom 0.125x0.125 smd: 1(-0.4,0) 2(0.4,0)
R0603
  rect 0.813x0.711 smd: 1(-0.737,0) 2(0.737,0)
R0603_H24
  rect 0.813x0.711 smd: 1(-0.737,0) 2(0.737,0)
R1206XI
  rect 0.914x1.6 smd: 1(-1.45,0) 2(1.45,0)
R1206XO_4P_SHORT
  rect 1.499x2.007 smd: 1A(-1.7,0) 2A(1.7,0)
  rect 0.254x0.508 smd: 1B(-1.078,0) 2B(1.078,0)
SC70-5XA
  rect 0.508x0.406 smd: 1(-0.95,0.65) 2(-0.95,0) 3(-0.95,-0.65) 4(0.95,-0.65) 5(0.95,0.65)
SOD123_2-65X1-6
  rect 1.499x1.499 smd: A(-1.95,0) C(1.95,0)
SOD123F
  rect 1.321x1.422 smd: A(-1.45,0) C(1.45,0)
SOD323XB
  rect 1.372x0.66 smd: 1(-1.2,0) 2(1.2,0)
SOIC8XH
  rect 1.27x0.889 smd: 1(-2.6,1.905) 2(-2.6,0.635) 3(-2.6,-0.635) 4(-2.6,-1.905) 5(2.6,-1.905) 6(2.6,-0.635) 7(2.6,0.635) 8(2.6,1.905)
SOT323XB
  rect 0.813x0.61 smd: D(0.8,0) G(-0.8,0.65) S(-0.8,-0.65)
SOT363_0-65_2X1-25XB
  rect 0.813x0.406 smd: 1(-0.95,0.65) 2(-0.95,0) 3(-0.95,-0.65) 4(0.95,-0.65) 5(0.95,0) 6(0.95,0.65)
SOT363XB
  rect 0.61x0.61 smd: 1(-0.9,0.75) 3(-0.9,-0.75) 4(0.9,-0.75) 6(0.9,0.75)
  rect 0.61x0.406 smd: 2(-0.9,0) 5(0.9,0)
TDR_3P_C85P67_141_100M_Q
  round 2.159 hole 1.702: 1(0,0) 2(-1.27,3.349) 3(1.27,3.349)
TRIANG_LAUNCH_3PXA
  round 0.254 hole 0.991 unplated: (-1.274,3.852) (-1.274,-2.498) (-0.004,-5.038) (1.266,3.852) (1.266,-2.498)
  round 0.66 smd: 1(-0.512,1.301) 2(0.504,1.301)
  rect 0.991x1.499 smd: 3(-0.004,-0.148)
TSSOP5
  rect 1.245x0.356 smd: 1(-0.945,0.65) 2(-0.945,0) 3(-0.945,-0.65) 4(0.945,-0.65) 5(0.945,0.65)
TSSOP24
  rect 1.499x0.356 smd: 1(-2.921,3.575) 2(-2.921,2.925) 3(-2.921,2.275) 4(-2.921,1.625) 5(-2.921,0.975) 6(-2.921,0.325) 7(-2.921,-0.325) 8(-2.921,-0.975) 9(-2.921,-1.625) 10(-2.921,-2.275) 11(-2.921,-2.925) 12(-2.921,-3.575) 13(2.921,-3.575) 14(2.921,-2.925) 15(2.921,-2.275) 16(2.921,-1.625) 17(2.921,-0.975) 18(2.921,-0.325) 19(2.921,0.325) 20(2.921,0.975) 21(2.921,1.625) 22(2.921,2.275) 23(2.921,2.925) 24(2.921,3.575)
unnamed#2
  round 0.991 smd: 1(0,0)
unnamed#3
  round 0 smd: (5,-5)
unnamed#4
  round 0 smd: (5,5)
unnamed#5
  round 0 smd: (-5,-5)
unnamed#6
  round 0 smd: (-5,5)
VFQFPN32_TH_0-5_5X5
  custom 0.07x0.07 smd: 1(-2.45,1.75) 2(-2.45,1.25) 3(-2.45,0.75) 4(-2.45,0.25) 5(-2.45,-0.25) 6(-2.45,-0.75) 7(-2.45,-1.25) 8(-2.45,-1.75) 9(-1.75,-2.45) 10(-1.25,-2.45) 11(-0.75,-2.45) 12(-0.25,-2.45) 13(0.25,-2.45) 14(0.75,-2.45) 15(1.25,-2.45) 16(1.75,-2.45) 17(2.45,-1.75) 18(2.45,-1.25) 19(2.45,-0.75) 20(2.45,-0.25) 21(2.45,0.25) 22(2.45,0.75) 23(2.45,1.25) 24(2.45,1.75) 25(1.75,2.45) 26(1.25,2.45) 27(0.75,2.45) 28(0.25,2.45) 29(-0.25,2.45) 30(-0.75,2.45) 31(-1.25,2.45) 32(-1.75,2.45)
  rect 3.302x3.302 smd: TH(0,0)
WSON8_TH_0-5_2X2XA
  custom 0.062x0.062 smd: 1(-0.95,0.75) 2(-0.95,0.25) 3(-0.95,-0.25) 4(-0.95,-0.75) 5(0.95,-0.75) 6(0.95,-0.25) 7(0.95,0.25) 8(0.95,0.75)
  custom 0.225x0.225 smd: TH(0,0)

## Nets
GND: C48.2 C49.2 C50.2 C51.2 C52.2 C53.2 C54.2 C55.2 C56.2 C57.2 C58.2 C59.2 C60.2 C61.2 C62.2 C63.2 C64.2 C65.2 C66.2 C67.2 C68.2 C69.2 C70.2 C71.2 C72.2 C73.2 C75.2 C76.2 C78.2 C79.2 C81.2 C82.2 C84.1 C85.2 C86.1 C87.1 C88.2 C89.2 C90.2 C91.2 C92.2 C96.1 C102.1 C105.1 C108.1 C109.2 C110.2 C111.2 C112.2 C113.1 C115.2 C116.1 C118.2 C119.1 C121.2 C122.1 C124.2 C125.1 C127.2 C128.1 C129.1 C130.1 C131.1 C132.1 C147.2 C148.2 C149.2 C150.2 C157.2 C158.2 C159.2 C160.2 C161.2 C162.2 C163.2 C164.1 C165.1 C166.1 C167.1 C168.1 C169.2 C170.1 C171.2 C172.2 C176.2 C177.2 C178.1 C179.1 C180.2 C202.2 C204.2 C205.2 C207.2 C208.2 C209.2 C210.2 C211.2 C212.2 C213.2 C214.2 C215.2 C216.2 C217.2 C218.2 C219.2 C220.2 C221.2 C222.2 C223.2 C224.2 C225.2 C226.2 C227.2 C228.2 C229.2 C230.2 C231.2 C232.2 C233.2 C234.2 C235.2 C236.2 C237.2 C239.2 C240.2 C243.2 C244.2 C246.2 C247.2 C249.2 C250.2 C251.2 C252.2 C284.1 C285.1 C286.1 C287.1 C288.1 C289.1 C290.1 C291.1 C292.1 C293.1 C294.1 C295.2 C296.1 C297.2 C298.2 C299.2 C300.2 C301.2 C302.2 C303.2 C304.2 C306.2 C307.2 C308.2 C309.2 C310.1 C311.2 C312.2 C313.2 C314.2 C315.2 C316.2 C317.2 C318.2 C319.2 C320.2 C321.2 C322.2 D2.A D3.A D4.A D5.A D6.A D7.A D8.A D9.A D10.2 D21.A D22.1 D22.2 D23.1 GF1.A1 GF1.A2 GF1.A3 GF1.A4 GF1.A5 GF1.A6 GF1.A13 GF1.A16 GF1.A19 GF1.A22 GF1.A25 GF1.A28 GF1.A29 GF1.A32 GF1.A35 GF1.A38 GF1.A41 GF1.A43 GF1.A46 GF1.A49 GF1.A52 GF1.A55 GF1.A58 GF1.A61 GF1.A64 GF1.A67 GF1.B13 GF1.B16 GF1.B19 GF1.B22 GF1.B25 GF1.B28 GF1.B29 GF1.B32 GF1.B35 GF1.B38 GF1.B41 GF1.B43 GF1.B46 GF1.B49 GF1.B52 GF1.B55 GF1.B58 GF1.B61 GF1.B64 GF1.B67 GF1.OCP_A10 GF1.OCP_A13 GF1.OCP_B10 GF1.OCP_B13 GF2.A1 GF2.A2 GF2.A3 GF2.A4 GF2.A5 GF2.A6 GF2.A13 GF2.A16 GF2.A19 GF2.A22 GF2.A25 GF2.A28 GF2.A29 GF2.A32 GF2.A35 GF2.A38 GF2.A41 GF2.A43 GF2.A46 GF2.A49 GF2.A52 GF2.A55 GF2.A58 GF2.A61 GF2.A64 GF2.A67 GF2.B13 GF2.B16 GF2.B19 GF2.B22 GF2.B25 GF2.B28 GF2.B29 GF2.B32 GF2.B35 GF2.B38 GF2.B41 GF2.B43 GF2.B46 GF2.B49 GF2.B52 GF2.B55 GF2.B58 GF2.B61 GF2.B64 GF2.B67 H3.1(\GND\) H4.1(\GND\) H5.1(\GND\) H6.1(\GND\) H7.1(\GND\) H8.1(\GND\) H9.1(\GND\) H10.1(\GND\) H11.1(\GND\) H12.1(\GND\) H13.1(\GND\) H14.1(\GND\) H15.1(\GND\) H16.1(\GND\) H17.1(\GND\) J1.2 J2.3 J2.5 J4.A1 J4.A2 J4.A3 J4.A4 J4.A5 J4.A6 J4.A13 J4.A16 J4.A19 J4.A22 J4.A25 J4.A28 J4.B13 J4.B16 J4.B19 J4.B22 J4.B25 J4.B28 J4.G1 J4.G2 J5.A1 J5.A2 J5.A3 J5.A4 J5.A5 J5.A6 J5.A13 J5.A16 J5.A19 J5.A22 J5.A25 J5.A28 J5.B13 J5.B16 J5.B19 J5.B22 J5.B25 J5.B28 J5.G1 J5.G2 J6.A1 J6.A2 J6.A3 J6.A4 J6.A5 J6.A6 J6.A13 J6.A16 J6.A19 J6.A22 J6.A25 J6.A28 J6.B13 J6.B16 J6.B19 J6.B22 J6.B25 J6.B28 J6.G1 J6.G2 J7.A1 J7.A2 J7.A3 J7.A4 J7.A5 J7.A6 J7.A13 J7.A16 J7.A19 J7.A22 J7.A25 J7.A28 J7.B13 J7.B16 J7.B19 J7.B22 J7.B25 J7.B28 J7.G1 J7.G2 OSC1.2 PC72.2 Q3.S(\S\) Q4.S(\S\) Q5.1 Q5.4 Q6.1 Q6.4 Q7.1 Q7.4 Q8.1 Q8.4 Q9.1 Q9.4 Q10.1 Q10.4 Q11.1 Q11.4 Q12.1 Q12.4 R11.2 R169.1 R172.1 R175.2 R176.2 R177.1 R180.1 R183.2 R184.2 R189.2 R192.2 R195.2 R196.2 R197.2 R198.2 R203.2 R204.2 R214.1 R221.2 R223.2 R229.1 R236.2 R237.2 R244.1 R252.2 R253.2 R259.1 R266.2 R267.2 R279.2 R280.2 R281.2 R284.1 R285.1 R292.2 R293.2 R294.2 R298.2 R306.2 R308.2 R417.2 R438.2 R441.2 R444.2 R445.2 R448.2 R449.2 R452.2 R453.2 R455.2 R457.2 R459.2 R461.2 R463.2 R464.2 R465.2 R466.2 R467.2 R474.2 R475.2 R477.2 R479.2 R481.2 R490.2 R492.2 R496.2 R497.2 R499.2 R500.2 R502.2 R503.2 R505.1 R509.2 R510.2 R511.2 R518.1 R520.2 R521.2 R522.1 R526.1 R527.1 R532.1 R562.2 R564.2 R567.1 R569.1 R570.1 R574.1 R575.1 R576.1 R577.2 R578.1 R617.1 R619.1 R651.2 R663.2 R675.1 R696.1 R699.1 R730.1 R731.1 R736.1 R737.1 R738.1 R749.2 R750.2 R753.2 R754.2 R756.2 R758.2 R760.2 R768.2 R769.2 R770.2 R772.2 R777.1 R778.2 R779.1 R780.1 R784.1 R785.1 R786.2 R787.1 R791.1 R4614.1 R4622.2 R4626.2 R4630.2 R4634.2 R4643.2 R4648.2 R4653.2 R4658.2 U3.8 U3.TH(\TH_GND\) U4.8 U4.TH(\TH_GND\) U5.8 U5.TH(\TH_GND\) U6.8 U6.TH(\TH_GND\) U7.8 U7.TH(\TH_GND\) U8.8 U8.TH(\TH_GND\) U9.8 U9.TH(\TH_GND\) U10.8 U10.TH(\TH_GND\) U11.10 U11.TH U12.10 U12.TH U13.10 U13.TH U14.10 U14.TH U15.4 U16.4 U17.S(\S\) U18.8 U18.TH(\TH_GND\) U22.A7 U22.B2 U22.B7 U22.C1 U22.C2 U23.A7 U23.B2 U23.B7 U23.C1 U23.C2 U24.A7 U24.B2 U24.B7 U24.C1 U24.C2 U25.A7 U25.B2 U25.B7 U25.C1 U25.C2 U26.A7 U26.B2 U26.B7 U26.C1 U26.C2 U27.A7 U27.B2 U27.B7 U27.C1 U27.C2 U28.A7 U28.B2 U28.B7 U28.C1 U28.C2 U29.A7 U29.B2 U29.B7 U29.C1 U29.C2 U30.A7 U30.B2 U30.B7 U30.C1 U30.C2 U32.8 U32.TH U33.A7 U33.B2 U33.B7 U33.C1 U33.C2 U34.2 U34.3 U34.7 U35.A1 U35.B7 U35.C6 U35.C7 U35.D6 U35.D7 U35.E6 U35.F3 U35.F6 U35.G6 U35.G7 U35.G8 U35.G9 U35.G10 U35.G11 U35.H6 U35.H7 U35.H8 U35.H9 U35.H10 U35.H11 U35.J6 U35.J7 U35.J8 U35.J9 U35.J10 U35.J11 U35.K6 U35.K7 U35.K8 U35.K9 U35.K10 U35.K11 U35.L6 U35.L7 U35.L8 U35.L9 U35.L10 U35.L11 U35.M7 U35.M8 U35.M9 U35.M10 U35.M11 U35.N13 U36.TH U42.3 U43.3 U44.5(\VSS\) U45.3 U46.3 U47.3 U48.2 U48.3 U48.12(\VSS\) U48.21
GND1: J8.3 J9.3 J10.3 J11.3 J12.1 J13.3 J14.3 J15.1 J16.1 J17.3 J18.3 J19.3 J20.3 J21.3 J22.3 J23.3 J24.3 J25.3 J26.3 J27.1 X1.2 X1.3 X2.2 X2.3 X3.2 X3.3 X4.2 X4.3 X5.2 X5.3 X6.2 X6.3 X7.2 X7.3 X8.2 X8.3
P1V2_ADJ: R663.1 R664.2 U36.4
P1V2_RST_PG: D25.2 R4609.1 R4610.1 R4611.2
P1V2_RST_PG_EN: C310.2 D25.1 R4610.2 U45.2
P1V2_RST_PG_R: R4611.1 U47.4(\Y\)
P1V2_STBY: C208.1 C209.1 C211.1 C220.1 C221.1 C222.1 C223.1 C224.1 C225.1 C226.1 C227.1 C249.1 C250.1 C301.1 L5.2 L8.2 R664.1 R4588.1 U35.F8 U35.F9 U35.F10 U35.G5 U35.H5 U35.H12 U35.H13 U35.J12 U35.K12 U35.M6 U35.N8 U35.N9(\VDDCORE_N9\) U36.1 U36.2 U36.3(\VOUT3\)
P1V2_STBY_BIC_SCALED: C296.2 R4588.2 U35.H2
P1V2_STBY_EN_R: PR76.2 U36.6
P1V2_VDD_PG_R: R794.1 U35.N3 U47.2
P3V3_AUX: C62.1 C63.1 C68.1 C69.1 C72.1 C75.1 C78.1 C81.1 C84.2 C85.1 C88.1 C89.1 C90.1 C91.1 C92.1 C113.2 C116.2 C119.2 C122.2 C164.2 C165.2 C166.2 C167.2 C210.1 C212.1 C213.1 C214.1 C215.1 C216.1 C217.1 C218.1 C219.1 C233.1 C234.1 C235.1 C251.1 C295.1 C297.1 C298.1 C299.1 C306.1 C307.1 C308.1 C309.1 C311.1 C314.1 D24.A J2.1 L4.1 L6.1 L7.2 L9.2 PC72.1 R90.1 R171.2 R174.2 R179.2 R182.2 R185.1 R190.1 R191.2 R193.2 R194.1 R199.1 R200.2 R201.1 R202.2 R217.2 R218.2 R219.2 R232.2 R233.2 R234.2 R247.2 R248.2 R249.2 R262.2 R263.2 R264.2 R273.1 R274.1 R275.1 R282.2 R283.2 R286.1 R287.1 R288.1 R295.2 R319.2 R410.2 R411.2 R412.2 R413.1 R414.2 R426.2 R427.2 R428.2 R429.2 R454.1 R456.1 R458.1 R460.1 R506.2 R512.1 R513.1 R519.2 R528.2 R533.2 R565.1 R566.1 R568.1 R571.1 R572.1 R573.1 R596.1 R598.1 R599.1 R600.1 R602.1 R604.1 R605.1 R607.1 R608.1 R611.1 R613.1 R627.1 R628.1 R629.1 R635.1 R636.1 R639.1 R640.1 R641.1 R646.1 R659.2 R697.1 R701.1 R707.1 R708.1 R713.1 R714.1 R733.2 R734.2 R735.2 R751.1 R773.2 R774.2 R775.2 R776.2 R781.2 R782.2 R783.2 R788.1 R789.2 R790.2 R4580.2 R4581.2 R4582.2 R4583.2 R4597.2 R4598.1 R4599.1 R4600.1 R4601.1 R4604.2 R4605.2 R4609.2 R4613.1 R4615.1 R4616.1 R4617.1 R4618.1 R4639.1 R4644.1 R4649.1 R4654.1 R4659.1 R4660.1 R4661.1 R4662.1 R4663.1 R4664.1 R4665.1 R4666.1 R4667.1 R4668.1 R4669.1 U7.3 U7.4 U8.3 U8.4 U9.3 U9.4 U10.3 U10.4 U11.9(\VS\) U12.9(\VS\) U13.9(\VS\) U14.9(\VS\) U15.8 U16.8(\V+\) U18.5 U26.A2(\VCC\) U26.A3 U26.A5 U26.B3 U26.B5 U26.C3 U26.C5 U26.D5 U27.A2(\VCC\) U27.A3 U27.A5 U27.B3 U27.B5 U27.C3 U27.C5 U27.D5 U28.A2(\VCC\) U28.A3 U28.A5 U28.B3 U28.B5 U28.C3 U28.C5 U28.D5 U29.A2(\VCC\) U29.A3 U29.A5 U29.B3 U29.B5 U29.C3 U29.C5 U29.D5 U30.A4 U30.B4 U30.B6 U30.C4 U30.C6 U30.D4 U30.D6 U35.E8 U35.E9 U35.E10 U35.F13 U35.G4 U35.G12 U35.G13 U35.H4 U35.K13 U35.L5 U35.L12 U35.L13 U35.N7 U35.N10 U36.7 U36.8 U36.9 U36.10 U42.5(\VCC\) U43.5(\VCC\) U44.10 U45.5 U46.5(\VCC\) U47.5 U48.24
P3V3_AUX_BIC_SCALED: C286.2 R751.2 R753.1 U35.E3
P3V3_DB800: C147.1 C148.1 C149.1 C150.1 L4.2 R476.1 R478.1 R480.1 R504.1 U32.11 U32.15 U32.25
P3V3_DB800A: C157.1 C158.1 C159.1 R504.2 U32.4 U32.21
P3V3_E1S_0: C64.1 J4.B11 R213.1 R215.2 R216.2 R767.1 U7.5 U26.A4 U26.B4 U26.B6 U26.C4 U26.C6 U26.D4 U26.D6
P3V3_E1S_0_CB: R455.1 U26.B1
P3V3_E1S_0_DVDT: C60.1 U7.1
P3V3_E1S_0_GATE: C115.1 U26.A6
P3V3_E1S_0_ILM: R189.1 U7.7
P3V3_E1S_0_ISENSE: R490.1 U26.A1
P3V3_E1S_0_OV: R491.2 R492.1 U26.D3
P3V3_E1S_0_REG: C128.2 U26.D1
P3V3_E1S_0_SCALED: C293.2 R767.2 R770.1 U35.D3
P3V3_E1S_1: C65.1 J5.B11 R228.1 R230.2 R231.2 R771.1 U8.5 U27.A4 U27.B4 U27.B6 U27.C4 U27.C6 U27.D4 U27.D6
P3V3_E1S_1_CB: R457.1 U27.B1
P3V3_E1S_1_DVDT: C61.1 U8.1
P3V3_E1S_1_GATE: C118.1 U27.A6
P3V3_E1S_1_ILM: R192.1 U8.7
P3V3_E1S_1_ISENSE: R496.1 U27.A1
P3V3_E1S_1_OV: R495.2 R497.1 U27.D3
P3V3_E1S_1_REG: C129.2 U27.D1
P3V3_E1S_1_SCALED: C294.2 R771.2 R772.1 U35.C2
P3V3_E1S_2: C71.1 J6.B11 R243.1 R245.2 R246.2 R746.1 U10.5 U28.A4 U28.B4 U28.B6 U28.C4 U28.C6 U28.D4 U28.D6
P3V3_E1S_2_CB: R459.1 U28.B1
P3V3_E1S_2_DVDT: C67.1 U10.1
P3V3_E1S_2_GATE: C121.1 U28.A6
P3V3_E1S_2_ILM: R198.1 U10.7
P3V3_E1S_2_ISENSE: R500.1 U28.A1
P3V3_E1S_2_OV: R498.2 R499.1 U28.D3
P3V3_E1S_2_REG: C130.2 U28.D1
P3V3_E1S_2_SCALED: C284.2 R746.2 R749.1 U35.D1
P3V3_E1S_3: C70.1 J7.B11 R258.1 R260.2 R261.2 R747.1 U9.5 U29.A4 U29.B4 U29.B6 U29.C4 U29.C6 U29.D4 U29.D6
P3V3_E1S_3_CB: R461.1 U29.B1
P3V3_E1S_3_DVDT: C66.1 U9.1
P3V3_E1S_3_GATE: C124.1 U29.A6
P3V3_E1S_3_ILM: R197.1 U9.7
P3V3_E1S_3_ISENSE: R503.1 U29.A1
P3V3_E1S_3_OV: R501.2 R502.1 U29.D3
P3V3_E1S_3_REG: C131.2 U29.D1
P3V3_E1S_3_SCALED: C285.2 R747.2 R750.1 U35.D2
P3V3_EDGE: C86.2 C125.2 C168.2 D21.C(\C\) GF1.B11 GF2.B11 R7.1 R21.1 R22.1 R23.1 R24.1 R305.1 R307.2 R462.1 U18.3 U18.4 U30.A2(\VCC\) U30.A3 U30.A5 U30.B3 U30.B5 U30.C3 U30.C5 U30.D5
P3V3_EDGE_CB: R463.1 U30.B1
P3V3_EDGE_E1S_EN: R305.2 R308.1 U18.2
P3V3_EDGE_GATE: C127.1 U30.A6
P3V3_EDGE_ISENSE: R475.1 U30.A1
P3V3_EDGE_OCP_DVDT: C87.2 U18.1
P3V3_EDGE_OCP_FLT_N: R307.1 R309.1 U18.6 U30.C7
P3V3_EDGE_OCP_ILM: R306.1 U18.7
P3V3_EDGE_OV: R473.2 R474.1 U30.D3
P3V3_EDGE_REG: C132.2 U30.D1
P3V3_EDGE_UV: R462.2 R473.1 U30.D2
P12V_AUX: C50.1 C52.1 C56.1 C58.1 C160.1 C161.1 C162.1 C163.1 C172.1 D2.C(\C\) D3.C(\C\) D6.C(\C\) D7.C(\C\) D22.3(\CATHOD\) R170.1 R173.1 R178.1 R181.1 R296.1 R297.1 R439.1 R442.1 R446.1 R450.1 R524.1 R525.1 R534.2 R535.2 R536.2 R537.2 R765.1 R4621.1 R4625.1 R4629.1 R4633.1 U3.3 U3.4 U4.3 U4.4 U5.3 U5.4 U6.3 U6.4 U22.A2(\VCC\) U22.A3 U22.A5 U22.B3 U22.B5 U22.C3 U22.C5 U22.D5 U23.A2(\VCC\) U23.A3 U23.A5 U23.B3 U23.B5 U23.C3 U23.C5 U23.D5 U24.A2(\VCC\) U24.A3 U24.A5 U24.B3 U24.B5 U24.C3 U24.C5 U24.D5 U25.A2(\VCC\) U25.A3 U25.A5 U25.B3 U25.B5 U25.C3 U25.C5 U25.D5 U33.A4 U33.B4 U33.B6 U33.C4 U33.C6 U33.D4 U33.D6 U34.13 U34.14 U34.15 U34.16 U34.17 U34.18 U34.19 U34.20
P12V_AUX_0_ISENSE: R511.1 U33.A1
P12V_AUX_CB: R510.1 U33.B1
P12V_AUX_EN_MP5022: R522.2 R523.2 R531.2 U34.1
P12V_AUX_FB_MP5022: R525.2 R526.2 U34.11
P12V_AUX_GATE: C171.1 U33.A6
P12V_AUX_HSC_PWRGD: R513.2 R514.1 U33.D7 U34.10
P12V_AUX_IMON_MP5022: C178.2 R520.1 U34.8
P12V_AUX_ISET_MP5022: R521.1 U34.5
P12V_AUX_OV: R508.2 R509.1 U33.D3
P12V_AUX_PD_MP5022: R524.2 U34.12
P12V_AUX_REG: C170.2 U33.D1
P12V_AUX_SS_MP5022: C177.1 U34.6
P12V_AUX_TIMER_MP5022: C179.2 U34.4
P12V_AUX_UV: R507.2 R508.1 R530.2 U33.D2
P12V_BIC_SCALED: C291.2 R765.2 R768.1 U35.B1
P12V_E1S_0: C51.1 C73.1 D4.C(\C\) R220.2A U3.5 U11.11 U22.A4 U22.B4 U22.B6 U22.C4 U22.C6 U22.D4 U22.D6
P12V_E1S_0_CB: R438.1 U22.B1
P12V_E1S_0_DVDT: C48.1 U3.1
P12V_E1S_0_GATE: C109.1 U22.A6
P12V_E1S_0_ILM: R169.2 U3.7
P12V_E1S_0_IN_N: C74.2 R227.2 U11.12
P12V_E1S_0_IN_P: C74.1 R226.2 U11.13
P12V_E1S_0_IN_SENN: R220.1B R227.1
P12V_E1S_0_IN_SENP: R220.2B(\2B\) R226.1
P12V_E1S_0_ISENSE: R464.1 U22.A1
P12V_E1S_0_L: J4.B1 J4.B2 J4.B3 J4.B4 J4.B5 J4.B6 R220.1A R752.1
P12V_E1S_0_OV: R440.2 R441.1 U22.D3
P12V_E1S_0_REG: C96.2 U22.D1
P12V_E1S_0_SCALED: C287.2 R752.2 R754.1 U35.J1
P12V_E1S_1: C53.1 C76.1 D5.C(\C\) R235.2A U4.5 U12.11 U23.A4 U23.B4 U23.B6 U23.C4 U23.C6 U23.D4 U23.D6
P12V_E1S_1_CB: R444.1 U23.B1
P12V_E1S_1_DVDT: C49.1 U4.1
P12V_E1S_1_GATE: C110.1 U23.A6
P12V_E1S_1_ILM: R172.2 U4.7
P12V_E1S_1_IN_N: C77.2 R242.2 U12.12
P12V_E1S_1_IN_P: C77.1 R241.2 U12.13
P12V_E1S_1_IN_SENN: R235.1B R242.1
P12V_E1S_1_IN_SENP: R235.2B(\2B\) R241.1
P12V_E1S_1_ISENSE: R465.1 U23.A1
P12V_E1S_1_L: J5.B1 J5.B2 J5.B3 J5.B4 J5.B5 J5.B6 R235.1A R755.1
P12V_E1S_1_OV: R443.2 R445.1 U23.D3
P12V_E1S_1_REG: C102.2 U23.D1
P12V_E1S_1_SCALED: C288.2 R755.2 R756.1 U35.K3
P12V_E1S_2: C57.1 C79.1 D8.C(\C\) R250.2A U5.5 U13.11 U24.A4 U24.B4 U24.B6 U24.C4 U24.C6 U24.D4 U24.D6
P12V_E1S_2_CB: R448.1 U24.B1
P12V_E1S_2_DVDT: C54.1 U5.1
P12V_E1S_2_GATE: C111.1 U24.A6
P12V_E1S_2_ILM: R177.2 U5.7
P12V_E1S_2_IN_N: C80.2 R257.2 U13.12
P12V_E1S_2_IN_P: C80.1 R256.2 U13.13
P12V_E1S_2_IN_SENN: R250.1B R257.1
P12V_E1S_2_IN_SENP: R250.2B(\2B\) R256.1
P12V_E1S_2_ISENSE: R466.1 U24.A1
P12V_E1S_2_L: J6.B1 J6.B2 J6.B3 J6.B4 J6.B5 J6.B6 R250.1A R759.1
P12V_E1S_2_OV: R447.2 R449.1 U24.D3
P12V_E1S_2_REG: C105.2 U24.D1
P12V_E1S_2_SCALED: C290.2 R759.2 R760.1 U35.K4
P12V_E1S_3: C59.1 C82.1 D9.C(\C\) R265.2A U6.5 U14.11 U25.A4 U25.B4 U25.B6 U25.C4 U25.C6 U25.D4 U25.D6
P12V_E1S_3_CB: R452.1 U25.B1
P12V_E1S_3_DVDT: C55.1 U6.1
P12V_E1S_3_GATE: C112.1 U25.A6
P12V_E1S_3_ILM: R180.2 U6.7
P12V_E1S_3_IN_N: C83.2 R272.2 U14.12
P12V_E1S_3_IN_P: C83.1 R271.2 U14.13
P12V_E1S_3_IN_SENN: R265.1B R272.1
P12V_E1S_3_IN_SENP: R265.2B(\2B\) R271.1
P12V_E1S_3_ISENSE: R467.1 U25.A1
P12V_E1S_3_L: J7.B1 J7.B2 J7.B3 J7.B4 J7.B5 J7.B6 R265.1A R757.1
P12V_E1S_3_OV: R451.2 R453.1 U25.D3
P12V_E1S_3_REG: C108.2 U25.D1
P12V_E1S_3_SCALED: C289.2 R757.2 R758.1 U35.K2
P12V_EDGE: C169.1 C176.1 D23.2 GF1.B1 GF1.B2 GF1.B3 GF1.B4 GF1.B5 GF1.B6 GF2.B1 GF2.B2 GF2.B3 GF2.B4 GF2.B5 GF2.B6 R507.1 R523.1 R529.1 R534.1 R535.1 R536.1 R537.1 R538.1 R766.1 U33.A3 U33.A5 U33.B3 U33.B5 U33.C3 U33.C5 U33.D5 U34.21_22 U34.23 U34.24 U34.25 U34.26(\VIN_EP4\)
P12V_EDGE_BIC_SCALED: C292.2 R766.2 R769.1 U35.C1
P12V_EDGE_R: C180.1 R538.2 U33.A2(\VCC\)
PVCC_1V2_PLL: C228.1 C229.1 C230.1 C231.1 L5.1 U35.G3
PVCC_BIC_SPI: C232.1 C300.1 R659.1 U35.B8
ADCVREFEXT0: U35.F2
ADCVREFEXT1: U35.G1
BIC_ADCAV33: C239.1 C240.1 C312.1 C313.1 L7.1 U35.J5 U35.K5
BIC_ADCVREFN0: C203.2 C204.1 U35.E1
BIC_ADCVREFN1: C206.2 C207.1 U35.H3
BIC_ADCVREFP0: C202.1 C203.1 U35.E2
BIC_ADCVREFP1: C205.1 C206.1 U35.J3
BIC_ESPI_SELECT: R775.1 R779.2 U35.D14
BIC_EXTRST_N: R5.1 R619.2 R4594.2 U35.B3
BIC_EXTRST_N_IO_EXP: R4592.2 R4599.2 R4603.1 U43.2
BIC_EXTRST_N_IO_EXP_R: R4592.1 U44.2 U48.5
BIC_EXTRST_N_R: R4594.1 U43.4
BIC_FWSPICK: J29.1 R651.1 R793.1 R797.2 U35.E7
BIC_FWSPICK_IO_EXP: R797.1 U44.3 U48.6
BIC_FWSPICK_R: J29.2 R646.2
BIC_FWSPICS1_N: R627.2 U35.F7
BIC_FWSPIDQ2: R628.2 U35.D8
BIC_FWSPIDQ3: R629.2 U35.D5
BIC_FWSPIMISO: R781.1 R784.2 U35.C8
BIC_MB_FWSPICK: GF1.OCP_B5 R793.2
BIC_SECUREBOOT: R773.1 R777.2 U35.B15
BIC_SP1_CS1: R636.2 U35.B6
BIC_SRST_N: R617.2 R792.1 R4587.2 R4593.2 U35.C3
BIC_SRST_N_IO_EXP: R4591.2 R4598.2 R4602.1 U42.1
BIC_SRST_N_IO_EXP_R: R4591.1 U44.1 U48.4
BIC_SRST_N_R: R4593.1 U42.4
BIC_USB2A_1V2: C243.1 C244.1 L8.1 U35.E5
BIC_USB2A_3V3: C246.1 C247.1 L9.1 U35.F5
BMC_HARTBEAT_LED: D24.C(\C\) R579.1
BMC_HARTBEAT_LED_R: R579.2 U35.A2
CARD_TYPE_R: GF1.OCP_A12 R7.2 R10.1 R11.1
CLK_25M_OSC_BIC_CLKIN: R660.2 U35.D4
CLK_25M_OSC_BIC_CLKOUT: OSC1.3 R660.1
CLK_100M_E1S_0_DN: J4.B14 U32.14
CLK_100M_E1S_0_DP: J4.B15 U32.13
CLK_100M_E1S_1_DN: J5.B14 U32.18
CLK_100M_E1S_1_DP: J5.B15 U32.17
CLK_100M_E1S_2_DN: J6.B14 U32.23
CLK_100M_E1S_2_DP: J6.B15 U32.22
CLK_100M_E1S_3_DN: J7.B14 U32.28
CLK_100M_E1S_3_DP: J7.B15 U32.27
CLK_100M_MB_DN: GF1.B14 U32.6
CLK_100M_MB_DP: GF1.B15 U32.5
CLKBUF_ADR0_TRI: R478.2 R479.1 U32.32
CLKBUF_E1S_0_OE_N: R630.2 U32.12
CLKBUF_E1S_0_OE_R_N: R630.1 R639.2 U35.A10
CLKBUF_E1S_1_OE_N: R631.2 U32.19
CLKBUF_E1S_1_OE_R_N: R631.1 R640.2 U35.B10
CLKBUF_E1S_2_OE_N: R632.2 U32.24
CLKBUF_E1S_2_OE_R_N: R632.1 R641.2 U35.A9
CLKBUF_E1S_3_OE_N: R724.2 U32.29
CLKBUF_E1S_3_OE_R_N: R724.1 R788.2 U35.B9
DELTA_L_85_5INCH_BOT_DN: J10.2 J11.1
DELTA_L_85_5INCH_BOT_DP: J10.1 J11.2
DELTA_L_85_5INCH_IN1_DN: J13.1 J14.2
DELTA_L_85_5INCH_IN1_DP: J13.2 J14.1
DELTA_L_85_5INCH_IN2_DN: J17.1 J18.2
DELTA_L_85_5INCH_IN2_DP: J17.2 J18.1
DELTA_L_85_5INCH_TOP_DN: J8.2 J9.1
DELTA_L_85_5INCH_TOP_DP: J8.1 J9.2
DELTA_L_85_10INCH_BOT_DN: J21.1 J22.2
DELTA_L_85_10INCH_BOT_DP: J21.2 J22.1
DELTA_L_85_10INCH_IN1_DN: J23.1 J24.2
DELTA_L_85_10INCH_IN1_DP: J23.2 J24.1
DELTA_L_85_10INCH_IN2_DN: J25.1 J26.2
DELTA_L_85_10INCH_IN2_DP: J25.2 J26.1
DELTA_L_85_10INCH_TOP_DN: J19.1 J20.2
DELTA_L_85_10INCH_TOP_DP: J19.2 J20.1
DUALPORT_N_E1S_0: J4.B9 R213.2 R214.2
DUALPORT_N_E1S_1: J5.B9 R228.2 R229.2
DUALPORT_N_E1S_2: J6.B9 R243.2 R244.2
DUALPORT_N_E1S_3: J7.B9 R258.2 R259.2
FM_AUX_PWR_EN: PR76.1 R15.1 U35.P6
FM_AUX_PWR_EN_R: GF1.B12 R15.2 R4607.2
FM_AUX_PWR_RST_EN: R4607.1 U46.2
FM_BOARD_ID_0: R738.2 R790.1 U35.R5
FM_BOARD_ID_1: R735.1 R737.2 U35.T4
FM_BOARD_ID_2: R734.1 R791.2 U35.P7
FM_BOARD_ID_3: R733.1 R736.2 U35.N6
FM_BOARD_REV_ID0: R283.1 R284.2 U35.C16
FM_BOARD_REV_ID1: R282.1 R285.2 U35.D16
FM_BOARD_REV_ID2: R505.2 R506.1 U35.D15
FM_CARD_TYPE: R10.2 U35.B2
FM_CLKBUF_EN: R476.2 R477.1 R626.1 U32.31
FM_CLKBUF_R_EN: R626.2 U35.F14
FM_FRU_WC_N: R276.1 U35.M1
FM_FRU_WC_N_R: R276.2 R414.1 R417.1 U15.7(\W\\C\\\)
FM_MB_SLOT_ID0: R8.1 R274.2 R280.1 U15.2 U35.R7
FM_MB_SLOT_ID1: R6.2 R273.2 R279.1 U15.3 U35.P11
FM_P3V3_E1S_0_EN: Q9.2 R633.2 R4640.1 R4643.1
FM_P3V3_E1S_0_EN_D: Q9.3 R4640.2 R4642.2
FM_P3V3_E1S_0_EN_G: Q9.5 R4641.1
FM_P3V3_E1S_0_EN_R_G: C319.1 Q9.6 R4639.2 R4641.2
FM_P3V3_E1S_0_R_EN: R633.1 U35.C9
FM_P3V3_E1S_0_SW_EN: R190.2 R195.1 R454.2 R491.1 R4642.1 U7.2 U26.D2
FM_P3V3_E1S_1_EN: Q10.2 R685.2 R4645.1 R4648.1
FM_P3V3_E1S_1_EN_D: Q10.3 R4645.2 R4647.2
FM_P3V3_E1S_1_EN_G: Q10.5 R4646.1
FM_P3V3_E1S_1_EN_R_G: C320.1 Q10.6 R4644.2 R4646.2
FM_P3V3_E1S_1_R_EN: R685.1 U35.D9
FM_P3V3_E1S_1_SW_EN: R194.2 R196.1 R456.2 R495.1 R4647.1 U8.2 U27.D2
FM_P3V3_E1S_2_EN: Q11.2 R634.2 R4650.1 R4653.1
FM_P3V3_E1S_2_EN_D: Q11.3 R4650.2 R4652.2
FM_P3V3_E1S_2_EN_G: Q11.5 R4651.1
FM_P3V3_E1S_2_EN_R_G: C321.1 Q11.6 R4649.2 R4651.2
FM_P3V3_E1S_2_R_EN: R634.1 U35.A8
FM_P3V3_E1S_2_SW_EN: R201.2 R204.1 R458.2 R498.1 R4652.1 U10.2 U28.D2
FM_P3V3_E1S_3_EN: Q12.2 R728.2 R4655.1 R4658.1
FM_P3V3_E1S_3_EN_D: Q12.3 R4655.2 R4657.2
FM_P3V3_E1S_3_EN_G: Q12.5 R4656.1
FM_P3V3_E1S_3_EN_R_G: C322.1 Q12.6 R4654.2 R4656.2
FM_P3V3_E1S_3_R_EN: R728.1 U35.M4
FM_P3V3_E1S_3_SW_EN: R199.2 R203.1 R460.2 R501.1 R4657.1 U9.2 U29.D2
FM_P3V3_E1S_EN_R: R731.2 U35.R9
FM_P12V_E1S_0_EN: Q5.2 R623.1 R4622.1 R4635.1
FM_P12V_E1S_0_EN_D: Q5.3 R4619.2 R4635.2
FM_P12V_E1S_0_EN_G: Q5.5 R4620.1
FM_P12V_E1S_0_EN_R_G: C315.1 Q5.6 R4620.2 R4621.2
FM_P12V_E1S_0_R_EN: R623.2 U35.E16
FM_P12V_E1S_0_SW_EN: R170.2 R175.1 R439.2 R440.1 R4619.1 U3.2 U22.D2
FM_P12V_E1S_1_EN: Q6.2 R624.1 R4626.1 R4636.1
FM_P12V_E1S_1_EN_D: Q6.3 R4623.2 R4636.2
FM_P12V_E1S_1_EN_G: Q6.5 R4624.1
FM_P12V_E1S_1_EN_R_G: C316.1 Q6.6 R4624.2 R4625.2
FM_P12V_E1S_1_R_EN: R624.2 U35.G14
FM_P12V_E1S_1_SW_EN: R173.2 R176.1 R442.2 R443.1 R4623.1 U4.2 U23.D2
FM_P12V_E1S_2_EN: Q7.2 R625.1 R4630.1 R4637.1
FM_P12V_E1S_2_EN_D: Q7.3 R4627.2 R4637.2
FM_P12V_E1S_2_EN_G: Q7.5 R4628.1
FM_P12V_E1S_2_EN_R_G: C317.1 Q7.6 R4628.2 R4629.2
FM_P12V_E1S_2_R_EN: R625.2 U35.F16
FM_P12V_E1S_2_SW_EN: R178.2 R183.1 R446.2 R447.1 R4627.1 U5.2 U24.D2
FM_P12V_E1S_3_EN: Q8.2 R727.1 R4634.1 R4638.1
FM_P12V_E1S_3_EN_D: Q8.3 R4631.2 R4638.2
FM_P12V_E1S_3_EN_G: Q8.5 R4632.1
FM_P12V_E1S_3_EN_R_G: C318.1 Q8.6 R4632.2 R4633.2
FM_P12V_E1S_3_R_EN: R727.2 U35.L3
FM_P12V_E1S_3_SW_EN: R181.2 R184.1 R450.2 R451.1 R4631.1 U6.2 U25.D2
FM_P12V_EDGE_EN: C302.1 Q4.G R729.1
FM_P12V_EDGE_EN_D: Q3.D R530.1 R531.1
FM_P12V_EDGE_EN_G: C303.1 Q3.G R4671.2
FM_P12V_EDGE_EN_R: R729.2 R730.2 U35.T10
FM_P12V_EDGE_EN_R_G: Q4.D R529.2 R4671.1
FM_POWER_EN: R2.1 U35.L2
FM_POWER_EN_R: GF1.OCP_B2 R2.2
FM_PRSNT_E1S_0_N: J4.A12 R555.2
FM_PRSNT_E1S_0_R_N: R555.1 R571.2 U35.R13
FM_PRSNT_E1S_1_N: J5.A12 R556.2
FM_PRSNT_E1S_1_R_N: R556.1 R572.2 U35.T14
FM_PRSNT_E1S_2_N: J6.A12 R557.2
FM_PRSNT_E1S_2_R_N: R557.1 R573.2 U35.T15
FM_PRSNT_E1S_3_N: J7.A12 R694.2
FM_PRSNT_E1S_3_R_N: R694.1 R697.2 U35.R14
FM_PWRDIS_E1S_0: J4.B12 R542.2
FM_PWRDIS_E1S_1: J5.B12 R544.2
FM_PWRDIS_E1S_2: J6.B12 R545.2
FM_PWRDIS_E1S_3: J7.B12 R700.2
FM_PWRDIS_E1S_R_0: R542.1 R565.2 U35.T7
FM_PWRDIS_E1S_R_1: R544.1 R566.2 U35.R8
FM_PWRDIS_E1S_R_2: R545.1 R568.2 U35.T8
FM_PWRDIS_E1S_R_3: R700.1 R701.2 U35.K1
HSC_SEL_ID0: R518.2 R519.1 U35.F11
HSC_SEL_ID1: R527.2 R528.1 U35.B16
HSC_SEL_ID2: R532.2 R533.1 U35.C15
INA230_E1S_0_A0: R219.1 R221.1 U11.2
INA230_E1S_0_A1: R218.1 R223.1 U11.1
INA230_E1S_0_ALERT_R_N: R217.1 R222.1 U11.3
INA230_E1S_1_A0: R234.1 R237.1 U12.2
INA230_E1S_1_A1: R233.1 R236.1 U12.1
INA230_E1S_1_ALERT_R_N: R232.1 R238.1 U12.3
INA230_E1S_2_A0: R249.1 R253.1 U13.2
INA230_E1S_2_A1: R248.1 R252.1 U13.1
INA230_E1S_2_ALERT_R_N: R247.1 R251.1 U13.3
INA230_E1S_3_A0: R264.1 R267.1 U14.2
INA230_E1S_3_A1: R263.1 R266.1 U14.1
INA230_E1S_3_ALERT_R_N: R262.1 R268.1 U14.3
IO_EXP_INT: R4604.1 U44.7 U48.1
IO_EXP_IO3: R4659.2 U48.7
IO_EXP_IO4: R4660.2 U48.8
IO_EXP_IO5: R4600.2 U48.9
IO_EXP_IO6: R4601.2 U48.10
IO_EXP_IO7: R4661.2 U48.11
IO_EXP_IO8: R4662.2 U48.13
IO_EXP_IO9: R4663.2 U48.14
IO_EXP_IO10: R4664.2 U48.15
IO_EXP_IO11: R4665.2 U48.16
IO_EXP_IO12: R4666.2 U48.17
IO_EXP_IO13: R4667.2 U48.18
IO_EXP_IO14: R4668.2 U48.19
IO_EXP_IO15: R4669.2 U48.20
IO_EXP_RST: R4605.1 U44.6
IO_EXP_U44_IO4: R4597.1 U44.4
IRQ_INA230_E1S_0_ALERT_N: R222.2 R620.1
IRQ_INA230_E1S_0_ALERT_R_N: R620.2 U35.E15
IRQ_INA230_E1S_1_ALERT_N: R238.2 R621.1
IRQ_INA230_E1S_1_ALERT_R_N: R621.2 U35.E14
IRQ_INA230_E1S_2_ALERT_N: R251.2 R622.1
IRQ_INA230_E1S_2_ALERT_R_N: R622.2 U35.E13
IRQ_INA230_E1S_3_ALERT_N: R268.2 R726.1
IRQ_INA230_E1S_3_ALERT_R_N: R726.2 U35.F15
IRQ_P3V3_E1S_0_FLT_N: R191.1 U7.6 U26.C7 U35.P2
IRQ_P3V3_E1S_1_FLT_N: R193.1 U8.6 U27.C7 U35.P3
IRQ_P3V3_E1S_2_FLT_N: R202.1 U10.6 U28.C7 U35.R1
IRQ_P3V3_E1S_3_FLT_N: R200.1 U9.6 U29.C7 U35.R2
IRQ_P3V3_EDGE_FLT_N: R309.2 U35.P10
